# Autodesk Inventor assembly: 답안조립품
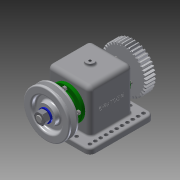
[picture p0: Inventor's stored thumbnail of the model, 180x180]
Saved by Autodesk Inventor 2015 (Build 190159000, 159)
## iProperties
Created: 2018-11
Part Number: 답안조립품
Document SubType Name: Assembly
Designer: now
Author: now
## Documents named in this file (13)
- C:\Users\now\Desktop\481108V1016\답안조립품.iam
- C:\Users\now\Desktop\481108V1016\V벨트풀리.ipt
- C:\Users\now\Desktop\481108V1016\너트 M12x1.25.ipt
- C:\Users\now\Desktop\481108V1016\베어링 6203.ipt
- C:\Users\now\Desktop\481108V1016\본체.ipt
- C:\Users\now\Desktop\481108V1016\볼트 M4.ipt
- C:\Users\now\Desktop\481108V1016\부시.ipt
- C:\Users\now\Desktop\481108V1016\스퍼기어.ipt
- C:\Users\now\Desktop\481108V1016\오일 실 26 38 8.ipt
- C:\Users\now\Desktop\481108V1016\와셔 12x24.ipt
- C:\Users\now\Desktop\481108V1016\축.ipt
- C:\Users\now\Desktop\481108V1016\커버.ipt
- C:\Users\now\Desktop\481108V1016\키 5x5x12.ipt
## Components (1 placed, 1 different names)
1. V벨트풀리:1 — 각도:3
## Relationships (1: Angle 1)
- 각도:3 [Angle]: V벨트풀리:1
